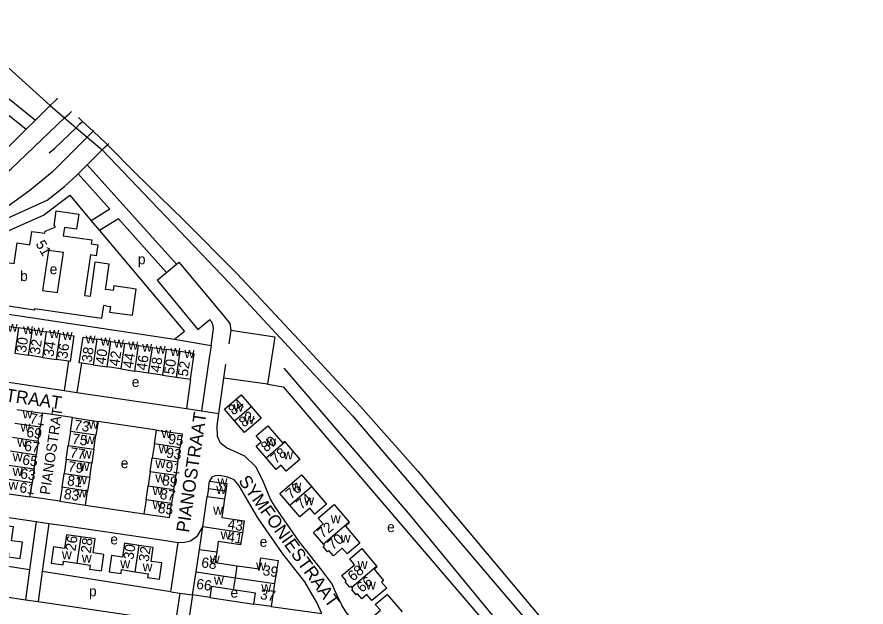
# Model space of a CAD drawing. Extents: x 163012 to 165277, y 382513 to 383987.
# Drawn here: x 164465.3 to 164795.7, y 383246.2 to 383475.9 of the extents above; entities that cross this region are included whole.
import ezdxf

# ---------------------------------------------------------------- set-up
doc = ezdxf.new("R2010")
doc.units = 0
for name, color, linetype in [('BLT_Basislijn', 7, 'Continuous'), ('BLT_Bebouwing', 7, 'Continuous'), ('BLT_Centroide', 7, 'Continuous'), ('BLT_Huisnummer', 7, 'Continuous'), ('BLT_Huisnummer_ tussenligend', 7, 'Continuous'), ('BLT_Onderverdeling_panden', 7, 'Continuous'), ('BLT_Spoorlijn', 7, 'Continuous'), ('BLT_Straatnaam', 7, 'Continuous'), ('BLT_Straatnaam_verkleind', 7, 'Continuous')]:
    doc.layers.add(name, color=color, linetype=linetype)

msp = doc.modelspace()

# ---------------------------------------------------------------- linework, layer by layer
at = {"layer": 'BLT_Basislijn'}
for p, q in [((164478.25, 383441.42), (164439.84, 383475.94)), ((164443.57, 383458.99), (164472.51, 383435.75)), ((164440.42, 383455.11), (164468.93, 383432.21)), ((164481.12, 383444.25), (164480.19, 383443.33)), ((164481.12, 383444.25), (164481.16, 383444.29)), ((164472.51, 383435.75), (164478.25, 383441.42)), ((164480.19, 383443.33), (164478.25, 383441.42)), ((164478.25, 383441.42), (164483.88, 383436.63)), ((164483.88, 383436.63), (164485.59, 383438.26)), ((164485.59, 383438.26), (164486.57, 383439.19)), ((164468.93, 383432.21), (164472.51, 383435.75)), ((164483.88, 383436.63), (164488.33, 383432.83)), ((164488.33, 383432.83), (164489.83, 383434.29)), ((164489.83, 383434.29), (164490.86, 383435.28)), ((164490.86, 383435.28), (164490.94, 383435.36)), ((164488.33, 383432.83), (164492.66, 383429.15)), ((164494.94, 383431.43), (164493.94, 383430.43)), ((164495.22, 383431.71), (164494.94, 383431.43)), ((164495.22, 383431.71), (164495.23, 383431.72)), ((164493.94, 383430.43), (164492.66, 383429.15)), ((164492.66, 383429.15), (164498.51, 383424.17)), ((164492.68, 383418.39), (164498.51, 383424.17)), ((164498.51, 383424.17), (164499.54, 383425.19)), ((164499.54, 383425.19), (164500.51, 383426.13)), ((164500.51, 383426.13), (164501.04, 383426.65)), ((164501.04, 383426.65), (164501.12, 383426.72)), ((164492.01, 383417.71), (164489.12, 383414.87)), ((164492.01, 383417.71), (164492.68, 383418.39)), ((164492.68, 383418.39), (164527.36, 383379.65)), ((164483.85, 383409.96), (164488.62, 383414.37)), ((164489.12, 383414.87), (164488.62, 383414.37)), ((164489.12, 383414.87), (164501.42, 383401.13)), ((164501.42, 383401.13), (164494.23, 383396.59)), ((164494.23, 383396.59), (164497.48, 383392.73)), ((164504.8, 383397.35), (164497.48, 383392.73)), ((164504.8, 383397.35), (164523.51, 383376.45)), ((164523.51, 383376.45), (164527.36, 383379.65)), ((164527.36, 383379.65), (164528.33, 383380.45)), ((164528.33, 383380.45), (164545.52, 383359.76)), ((164526.66, 383350.3), (164436.89, 383363.9)), ((164540.84, 383347.9), (164541.69, 383353.59)), ((164548.52, 383353.98), (164547.82, 383348.68)), ((164540.84, 383347.9), (164526.66, 383350.3)), ((164485.44, 383341.88), (164483.68, 383330.5)), ((164430.95, 383338.32), (164483.68, 383330.5)), ((164490.44, 383341.14), (164488.63, 383329.76)), ((164545.83, 383335.34), (164546.64, 383340.77)), ((164569.12, 383339.18), (164618.34, 383281.77)), ((164532.79, 383334.87), (164531.23, 383323.44)), ((164543.87, 383321.57), (164545.83, 383335.34)), ((164562.8, 383332.89), (164545.83, 383335.34)), ((164483.68, 383330.5), (164488.63, 383329.76)), ((164488.63, 383329.76), (164531.23, 383323.44)), ((164486.91, 383319.94), (164475.22, 383321.64)), ((164531.23, 383323.44), (164537.09, 383322.57)), ((164537.09, 383322.57), (164543.87, 383321.57)), ((164519.59, 383315.1), (164496.87, 383318.46)), ((164482.05, 383287.35), (164470.37, 383289.07)), ((164422.18, 383286.98), (164472.78, 383279.48)), ((164492.02, 383285.89), (164514.74, 383282.51)), ((164472.78, 383279.48), (164470.22, 383260.71)), ((164472.78, 383279.48), (164477.73, 383278.74)), ((164477.73, 383278.74), (164475.16, 383260)), ((164618.34, 383281.77), (164675.25, 383212.82)), ((164525.25, 383252.1), (164528.08, 383271.3)), ((164470.22, 383260.71), (164419.17, 383268.26)), ((164470.22, 383260.71), (164468.61, 383248.99)), ((164475.16, 383260), (164473.56, 383248.26)), ((164525.25, 383252.1), (164475.16, 383260)), ((164415.81, 383256.75), (164468.61, 383248.99)), ((164468.61, 383248.99), (164473.56, 383248.26)), ((164525.25, 383252.1), (164528.72, 383251.59)), ((164528.72, 383251.59), (164527.05, 383240.36)), ((164528.72, 383251.59), (164533.67, 383250.86)), ((164533.67, 383250.86), (164532, 383239.63)), ((164540.41, 383249.85), (164557.47, 383247.29)), ((164473.56, 383248.26), (164527.05, 383240.36)), ((164564.25, 383246.32), (164583.93, 383243.61))]:
    msp.add_line(p, q, dxfattribs=at)
for points in [[(164442.4, 383407.17), (164446.92, 383403.55), (164463.13, 383416.86), (164483.88, 383436.63)], [(164442.4, 383407.17), (164451.54, 383415.02), (164468.93, 383432.21)], [(164477.83, 383422.99), (164479.91, 383424.68), (164488.33, 383432.83)], [(164492.66, 383429.15), (164478.98, 383415.5), (164470.27, 383408.43), (164454.19, 383396.85), (164454, 383394.51)], [(164498.51, 383424.17), (164547.81, 383372.55), (164595.93, 383320.58), (164677.22, 383225), (164784.15, 383095.87), (164929, 382921.99), (164952.41, 382895.74), (164958.39, 382890.52), (164962.03, 382886.31)], [(164454, 383394.51), (164457.22, 383395.68), (164477.05, 383404.62), (164483.85, 383409.96)], [(164425.29, 383365.33), (164421.18, 383374.61), (164475.67, 383398.71), (164485.85, 383406.54), (164494.23, 383396.59)], [(164497.48, 383392.73), (164530.5, 383353.5), (164526.66, 383350.3)], [(164519.83, 383373.4), (164523.51, 383376.45)], [(164519.83, 383373.4), (164535.66, 383354.18), (164540.33, 383358.14)], [(164541.69, 383353.59), (164541.71, 383353.85), (164541.73, 383354.1), (164541.75, 383354.36), (164541.77, 383354.61), (164541.78, 383354.87), (164541.73, 383355.13), (164541.69, 383355.39), (164541.65, 383355.65), (164541.6, 383355.91), (164541.53, 383356.16), (164541.42, 383356.4), (164541.32, 383356.64), (164541.21, 383356.88), (164541.1, 383357.12), (164540.96, 383357.33), (164540.8, 383357.53), (164540.65, 383357.73), (164540.49, 383357.94), (164540.33, 383358.14)], [(164545.52, 383359.76), (164548.21, 383356.52), (164548.52, 383353.98)], [(164548.52, 383353.98), (164565.67, 383351.32), (164562.8, 383332.89)], [(164540.84, 383347.9), (164540.25, 383343.92), (164537.09, 383322.57)], [(164562.8, 383332.89), (164568.93, 383331.94), (164670.85, 383212.75), (164670.97, 383212.04)], [(164607.92, 383222.62), (164607.01, 383225.56), (164605.47, 383228.83), (164602.51, 383233.14), (164598.6, 383237.85), (164593.37, 383244.13), (164591.74, 383246.83), (164589.96, 383250.69), (164587.82, 383255.29), (164583.93, 383260.51), (164575.19, 383271.62), (164565.77, 383285.23), (164564.04, 383288.21), (164560.96, 383295.47), (164558.3, 383300.8), (164554.01, 383304.97), (164546.83, 383308.1), (164544.52, 383310.04), (164543.38, 383312.54), (164543.19, 383316.78), (164543.87, 383321.57)], [(164583.93, 383243.61), (164582.01, 383247.92), (164577.33, 383255.95), (164568.75, 383266.86), (164559.01, 383280.94), (164551.84, 383293.3), (164549.85, 383295.64), (164547.05, 383296.9), (164544.02, 383297.39), (164542.43, 383297.3), (164541.15, 383296.74), (164540.25, 383295.22)], [(164477.73, 383278.74), (164482.67, 383278.03), (164522.34, 383272.15), (164528.08, 383271.3)], [(164528.08, 383271.3), (164530.46, 383271.42), (164532.79, 383271.95), (164535.59, 383273.85), (164537.6, 383277.36)]]:
    msp.add_lwpolyline(points, dxfattribs=at)
at = {"layer": 'BLT_Bebouwing'}
for p, q in [((164499.78, 383369.86), (164500, 383371.4)), ((164500, 383369.83), (164499.78, 383369.86)), ((164498.97, 383363.55), (164498.26, 383358.53)), ((164500, 383363.4), (164498.97, 383363.55)), ((164460.52, 383355.73), (164465.92, 383354.93)), ((164471.32, 383354.13), (164465.92, 383354.93)), ((164471.32, 383354.13), (164476.72, 383353.33)), ((164482.12, 383352.53), (164476.72, 383353.33)), ((164501.83, 383349.61), (164496.43, 383350.41)), ((164501.83, 383349.61), (164507.23, 383348.81)), ((164512.63, 383348.01), (164507.23, 383348.81)), ((164512.63, 383348.01), (164518.03, 383347.21)), ((164464.45, 383344.99), (164469.85, 383344.19)), ((164518.03, 383347.21), (164523.44, 383346.41)), ((164528.84, 383345.61), (164523.44, 383346.41)), ((164475.25, 383343.39), (164469.85, 383344.19)), ((164475.25, 383343.39), (164480.65, 383342.59)), ((164485.44, 383341.88), (164480.65, 383342.59)), ((164494.96, 383340.47), (164490.44, 383341.14)), ((164494.96, 383340.47), (164500.36, 383339.67)), ((164505.76, 383338.87), (164500.36, 383339.67)), ((164505.76, 383338.87), (164511.16, 383338.07)), ((164516.56, 383337.27), (164511.16, 383338.07)), ((164521.96, 383336.47), (164516.56, 383337.27)), ((164521.96, 383336.47), (164527.36, 383335.67)), ((164465.26, 383323.12), (164475.22, 383321.64)), ((164475.22, 383321.64), (164474.41, 383316.22)), ((164486.1, 383314.51), (164486.91, 383319.94)), ((164486.91, 383319.94), (164496.87, 383318.46)), ((164496.87, 383318.46), (164496.06, 383313.04)), ((164473.6, 383310.79), (164474.41, 383316.22)), ((164518.78, 383309.66), (164519.59, 383315.1)), ((164519.59, 383315.1), (164529.55, 383313.61)), ((164486.1, 383314.51), (164485.29, 383309.08)), ((164495.25, 383307.6), (164496.06, 383313.04)), ((164529.55, 383313.61), (164528.75, 383308.19)), ((164473.6, 383310.79), (164472.79, 383305.36)), ((164484.48, 383303.65), (164485.29, 383309.08)), ((164518.78, 383309.66), (164517.97, 383304.23)), ((164471.99, 383299.93), (164472.79, 383305.36)), ((164495.25, 383307.6), (164494.45, 383302.17)), ((164527.94, 383302.76), (164528.75, 383308.19)), ((164484.48, 383303.65), (164483.67, 383298.21)), ((164493.64, 383296.74), (164494.45, 383302.17)), ((164517.17, 383298.8), (164517.97, 383304.23)), ((164527.94, 383302.76), (164527.13, 383297.33)), ((164471.99, 383299.93), (164471.18, 383294.49)), ((164517.17, 383298.8), (164516.36, 383293.37)), ((164482.86, 383292.78), (164483.67, 383298.21)), ((164493.64, 383296.74), (164492.83, 383291.31)), ((164526.32, 383291.9), (164527.13, 383297.33)), ((164539.8, 383292.22), (164540.25, 383295.22)), ((164470.37, 383289.07), (164471.18, 383294.49)), ((164482.86, 383292.78), (164482.05, 383287.35)), ((164515.55, 383287.94), (164516.36, 383293.37)), ((164526.32, 383291.9), (164525.51, 383286.47)), ((164539.8, 383292.22), (164539.36, 383289.25)), ((164460.4, 383290.54), (164470.37, 383289.07)), ((164492.02, 383285.89), (164492.83, 383291.31)), ((164537.6, 383277.36), (164539.36, 383289.25)), ((164546.54, 383291.22), (164546.11, 383288.25)), ((164482.05, 383287.35), (164492.02, 383285.89)), ((164515.55, 383287.94), (164514.74, 383282.51)), ((164524.71, 383281.05), (164525.51, 383286.47)), ((164514.74, 383282.51), (164524.71, 383281.05)), ((164536.3, 383268.6), (164537.6, 383277.36)), ((164543.65, 383271.66), (164543.05, 383267.6)), ((164535, 383259.85), (164536.3, 383268.6)), ((164533.67, 383250.86), (164535, 383259.85)), ((164565.58, 383255.32), (164564.25, 383246.32)), ((164540.41, 383249.85), (164533.67, 383250.86)), ((164564.25, 383246.32), (164557.47, 383247.29))]:
    msp.add_line(p, q, dxfattribs=at)
for points in [[(164445.85, 383365.73), (164448.2, 383382.26), (164464.26, 383379.98), (164465.4, 383387.97), (164470.33, 383387.27), (164471.06, 383392.44), (164476.19, 383391.71), (164476.3, 383392.47), (164480.14, 383394.04), (164480.24, 383394.52), (164479.74, 383394.63), (164480.6, 383400.43), (164489.39, 383399.13), (164488.53, 383393.29), (164483.85, 383393.94), (164483.29, 383390.7), (164494.41, 383389.12), (164494.19, 383387.59), (164496.79, 383387.22), (164496.19, 383382.97), (164493.96, 383383.29)], [(164493.97, 383383.3), (164491.62, 383367.51), (164493.9, 383367.19), (164495.77, 383380.43)], [(164500, 383371.4), (164501.18, 383379.66), (164495.77, 383380.43)], [(164500, 383363.4), (164501.68, 383363.14), (164501.38, 383361.03), (164510.23, 383359.78), (164511.68, 383370), (164502.99, 383371.24), (164502.74, 383369.48), (164500, 383369.83)], [(164498.26, 383358.53), (164472.16, 383362.24), (164472.1, 383361.83), (164445.85, 383365.73)], [(164482.12, 383352.53), (164487.48, 383351.74)], [(164487.48, 383351.74), (164486.01, 383341.8), (164485.44, 383341.88)], [(164490.44, 383341.14), (164489.56, 383341.27), (164491.03, 383351.21)], [(164491.03, 383351.21), (164496.43, 383350.41)], [(164534.26, 383344.81), (164528.84, 383345.61)], [(164532.79, 383334.87), (164534.26, 383344.81)], [(164527.36, 383335.67), (164532.79, 383334.87)], [(164549.97, 383318.71), (164546.07, 383323.26), (164552.58, 383328.82), (164556.47, 383324.28)], [(164556.47, 383324.28), (164560.36, 383319.74), (164553.86, 383314.18), (164549.97, 383318.71)], [(164562.33, 383304.28), (164558.44, 383308.81), (164558.44, 383308.81), (164560.38, 383310.48), (164558.41, 383312.77), (164562.97, 383316.67), (164562.97, 383316.67), (164568.68, 383310.06), (164569.45, 383310.71), (164569.6, 383310.52)], [(164569.6, 383310.52), (164569.6, 383310.52), (164575.45, 383303.65), (164570.11, 383299.11), (164568.16, 383301.4), (164566.22, 383299.75), (164562.33, 383304.28), (164562.33, 383304.28)], [(164540.25, 383295.22), (164546.98, 383294.22), (164546.54, 383291.22)], [(164571.53, 383285.85), (164567.63, 383290.39), (164567.63, 383290.39), (164576.05, 383297.61), (164579.95, 383293.07)], [(164579.95, 383293.07), (164585.8, 383286.25), (164585.8, 383286.25), (164581.24, 383282.34), (164579.3, 383284.61), (164579.3, 383284.61), (164575.43, 383281.31), (164571.53, 383285.85)], [(164546.11, 383288.25), (164545.06, 383281.02), (164553.76, 383279.73), (164553.07, 383275.07)], [(164584.55, 383270.66), (164580.66, 383275.21), (164584.5, 383278.5), (164582.55, 383280.79), (164582.55, 383280.79), (164582.55, 383280.79), (164588.79, 383286.09), (164588.79, 383286.09), (164594.61, 383279.27)], [(164594.61, 383279.27), (164594.77, 383279.08), (164593.11, 383277.66), (164593.11, 383277.66), (164598.79, 383271.03), (164593.88, 383266.82), (164591.93, 383269.11), (164588.44, 383266.12), (164586.72, 383268.12), (164586.21, 383267.68), (164584.45, 383269.76), (164584.94, 383270.2), (164584.55, 383270.66)], [(164456.9, 383267.98), (164462.1, 383267.17), (164461.88, 383265.69), (164466.52, 383265.02), (164467.44, 383271.39), (164463.23, 383271.99), (164463.99, 383277.36), (164458.43, 383278.19)], [(164490.17, 383273.48), (164484.59, 383274.31), (164483.79, 383268.95), (164479.56, 383269.59), (164478.62, 383263.23), (164483.26, 383262.54), (164483.48, 383264.02), (164488.65, 383263.22)], [(164488.65, 383263.22), (164493.81, 383262.42), (164493.6, 383260.94), (164498.27, 383260.31), (164499.19, 383266.68), (164494.98, 383267.29), (164495.74, 383272.66), (164490.17, 383273.48)], [(164553.07, 383275.07), (164552.37, 383270.37), (164543.65, 383271.66)], [(164512.72, 383270.14), (164507.15, 383270.97), (164506.35, 383265.62), (164502.11, 383266.25), (164501.17, 383259.92), (164505.81, 383259.24), (164506.03, 383260.72), (164511.2, 383259.92)], [(164511.2, 383259.92), (164516.36, 383259.11), (164516.14, 383257.63), (164520.83, 383256.97), (164521.74, 383263.34), (164517.53, 383263.95), (164518.29, 383269.31), (164512.72, 383270.14)], [(164595.67, 383253.87), (164595.3, 383254.31), (164594.8, 383253.88), (164592.99, 383255.97), (164593.49, 383256.4), (164593.49, 383256.4), (164591.75, 383258.41), (164591.75, 383258.41), (164596.73, 383262.66), (164594.79, 383264.94), (164599.46, 383268.92), (164605.25, 383262.09), (164605.25, 383262.09)], [(164543.05, 383267.6), (164542.44, 383263.51), (164551, 383262.24)], [(164551, 383262.24), (164559.53, 383260.98), (164560.18, 383265.29), (164566.91, 383264.3), (164565.58, 383255.32)], [(164605.25, 383262.09), (164605.25, 383262.09), (164605.46, 383261.85), (164604.3, 383260.87), (164604.3, 383260.87), (164608.01, 383256.5), (164607.24, 383255.85), (164609.2, 383253.55), (164609.2, 383253.55), (164603.45, 383248.68), (164601.51, 383250.98), (164599.56, 383249.31), (164597.86, 383251.29), (164597.36, 383250.86), (164595.57, 383252.95), (164596.07, 383253.39), (164595.67, 383253.87), (164595.67, 383253.87)], [(164549.61, 383252.88), (164541.05, 383254.15), (164540.41, 383249.85)], [(164557.47, 383247.29), (164558.15, 383251.62), (164549.61, 383252.88)], [(164606.79, 383237.05), (164602.89, 383241.6), (164606.73, 383244.88), (164604.76, 383247.16), (164604.76, 383247.16), (164609.33, 383251.08), (164615.2, 383244.26)]]:
    msp.add_lwpolyline(points, dxfattribs=at)
msp.add_lwpolyline([(164477.63, 383385.06), (164475.31, 383369.49), (164481.14, 383368.62), (164483.45, 383384.19)], close=True, dxfattribs=at)
at = {"layer": 'BLT_Onderverdeling_panden'}
for p, q in [((164465.92, 383354.93), (164464.45, 383344.99)), ((164469.85, 383344.19), (164471.32, 383354.13)), ((164476.72, 383353.33), (164475.25, 383343.39)), ((164480.65, 383342.59), (164482.12, 383352.53)), ((164496.43, 383350.41), (164494.96, 383340.47)), ((164500.36, 383339.67), (164501.83, 383349.61)), ((164507.23, 383348.81), (164505.76, 383338.87)), ((164511.16, 383338.07), (164512.63, 383348.01)), ((164516.56, 383337.27), (164518.03, 383347.21)), ((164523.44, 383346.41), (164521.96, 383336.47)), ((164527.36, 383335.67), (164528.84, 383345.61)), ((164549.97, 383318.71), (164556.47, 383324.28)), ((164474.41, 383316.22), (164464.45, 383317.69)), ((164463.64, 383312.26), (164473.6, 383310.79)), ((164496.06, 383313.04), (164486.1, 383314.51)), ((164485.29, 383309.08), (164495.25, 383307.6)), ((164528.75, 383308.19), (164518.78, 383309.66)), ((164472.79, 383305.36), (164462.83, 383306.83)), ((164494.45, 383302.17), (164484.48, 383303.65)), ((164517.97, 383304.23), (164527.94, 383302.76)), ((164462.02, 383301.4), (164471.99, 383299.93)), ((164527.13, 383297.33), (164517.17, 383298.8)), ((164471.18, 383294.49), (164461.21, 383295.97)), ((164483.67, 383298.21), (164493.64, 383296.74)), ((164492.83, 383291.31), (164482.86, 383292.78)), ((164516.36, 383293.37), (164526.32, 383291.9)), ((164546.54, 383291.22), (164539.8, 383292.22)), ((164539.36, 383289.25), (164546.11, 383288.25)), ((164525.51, 383286.47), (164515.55, 383287.94)), ((164594.61, 383279.27), (164584.55, 383270.66)), ((164553.07, 383275.07), (164537.6, 383277.36)), ((164490.17, 383273.48), (164488.65, 383263.22)), ((164512.72, 383270.14), (164511.2, 383259.92)), ((164536.3, 383268.6), (164543.05, 383267.6)), ((164550.31, 383257.58), (164551, 383262.24)), ((164535, 383259.85), (164550.31, 383257.58)), ((164595.67, 383253.87), (164605.25, 383262.09)), ((164549.61, 383252.88), (164550.31, 383257.58)), ((164550.31, 383257.58), (164565.58, 383255.32))]:
    msp.add_line(p, q, dxfattribs=at)
for points in [[(164562.33, 383304.28), (164562.33, 383304.28), (164569.6, 383310.52), (164569.6, 383310.52)], [(164571.53, 383285.85), (164571.53, 383285.85), (164579.95, 383293.07), (164579.95, 383293.07)]]:
    msp.add_lwpolyline(points, dxfattribs=at)
at = {"layer": 'BLT_Spoorlijn'}
for points in [[(164489.32, 383436.74), (164490.86, 383435.28)], [(164490.86, 383435.28), (164494.94, 383431.43)], [(164494.94, 383431.43), (164500, 383426.64)], [(164500.51, 383426.13), (164500, 383426.64)], [(164580.53, 383344.18), (164551.04, 383375.93), (164530.09, 383396.89), (164511.43, 383415.15), (164500.51, 383426.13)], [(164580.53, 383344.18), (164598.99, 383324.26), (164621.39, 383298.94), (164677.23, 383232.33)]]:
    msp.add_lwpolyline(points, dxfattribs=at)

# ---------------------------------------------------------------- texts
at = {"layer": 'BLT_Centroide'}
for s, p in [('p', (164512.37, 383379.63)), ('e', (164478.06, 383375.75)), ('b', (164466.55, 383373.1)), ('w', (164461.68, 383353.33)), ('w', (164467.71, 383352.44)), ('w', (164471.85, 383351.82)), ('w', (164477.92, 383350.92)), ('w', (164483.09, 383350.16)), ('w', (164492.05, 383348.83)), ('w', (164497.86, 383347.97)), ('w', (164503.09, 383347.2)), ('w', (164508.62, 383346.38)), ('w', (164514.05, 383345.57)), ('w', (164519.32, 383344.79)), ('w', (164525.04, 383343.95)), ('w', (164530.52, 383343.14)), ('e', (164510.01, 383331.84)), ('w', (164549.57, 383322.21)), ('w', (164467.53, 383319.6)), ('w', (164493.12, 383315.59)), ('w', (164553.79, 383317.42)), ('w', (164466.7, 383314.45)), ('w', (164521.52, 383312.01)), ('w', (164491.76, 383309.6)), ('w', (164562.24, 383308.63)), ('w', (164465.41, 383308.54)), ('w', (164520.46, 383306.03)), ('w', (164463.67, 383302.94)), ('w', (164490.55, 383304)), ('w', (164568.91, 383303.62)), ('w', (164489.64, 383299.15)), ('e', (164505.7, 383300.24)), ('w', (164519.18, 383300.27)), ('w', (164463.67, 383297.18)), ('w', (164488.73, 383293.93)), ('w', (164519.18, 383294.74)), ('w', (164543.35, 383293.22)), ('w', (164462, 383291.81)), ('w', (164488.73, 383288.85)), ('w', (164518.12, 383289.74)), ('w', (164542.89, 383290.16)), ('w', (164572.14, 383291.49)), ('w', (164577.08, 383285.82)), ('w', (164518.12, 383284.29)), ('w', (164541.66, 383282.12)), ('w', (164587.43, 383278.76)), ('w', (164544.58, 383272.53)), ('e', (164609.36, 383275.34)), ('e', (164501.66, 383270.56)), ('e', (164559.77, 383269.61)), ('w', (164591.31, 383271.19)), ('w', (164482.8, 383264.78)), ('w', (164490.55, 383263.41)), ('w', (164540.38, 383263.12)), ('w', (164505.52, 383261.22)), ('w', (164514.21, 383260.04)), ('w', (164558.41, 383260.31)), ('w', (164597.88, 383260.97)), ('w', (164541.97, 383254.88)), ('w', (164601.1, 383252.92)), ('p', (164493.36, 383250.33)), ('e', (164548.42, 383249.81)), ('w', (164560.41, 383251.97))]:
    msp.add_text(s, height=4, dxfattribs=at).set_placement(p)
at = {"layer": 'BLT_Huisnummer'}
for s, rotation, p in [('51', 300.4122, (164472.43, 383387.57)), ('30', 81.5821, (164468.83, 383345.04)), ('34', 81.5821, (164479.52, 383343.46)), ('38', 81.5821, (164494.38, 383341.27)), ('42', 81.5821, (164505.07, 383339.71)), ('46', 81.5821, (164515.75, 383338.1)), ('50', 81.5821, (164526.43, 383336.53)), ('52', 81.5821, (164531.78, 383335.76)), ('84', 39.8502, (164549.57, 383320.64)), ('71', 351.5821, (164470.09, 383317.76)), ('82', 39.8502, (164553.7, 383315.96)), ('73', 351.5821, (164487.37, 383315.2)), ('95', 351.5821, (164523.97, 383309.79)), ('80', 39.8502, (164562.28, 383306.26)), ('77', 351.5821, (164485.71, 383304.46)), ('65', 351.5821, (164467.21, 383301.71)), ('78', 39.8502, (164566.07, 383301.73)), ('89', 351.5821, (164521.57, 383293.66)), ('61', 351.5821, (164466.1, 383290.89)), ('83', 351.5821, (164483.38, 383288.33)), ('76', 39.8502, (164571.92, 383288.01)), ('74', 39.8502, (164576, 383283.9)), ('85', 351.5821, (164519.98, 383282.91)), ('43', 351.5816, (164547.1, 383276.62)), ('72', 39.8502, (164584.24, 383272.75)), ('41', 351.6879, (164546.93, 383271.66)), ('26', 81.5821, (164488.06, 383267.77)), ('28', 81.5821, (164493.99, 383266.9)), ('70', 39.8502, (164588.21, 383268.21)), ('30', 81.5821, (164510.61, 383264.44)), ('32', 81.5821, (164516.55, 383263.58)), ('68', 352.0077, (164536.87, 383261.65)), ('39', 351.5816, (164560.75, 383258.61)), ('68', 39.8502, (164596.1, 383256.01)), ('66', 351.5816, (164534.91, 383253.31)), ('66', 39.8502, (164599.55, 383251.62)), ('37', 351.5816, (164559.76, 383249.29))]:
    msp.add_text(s, height=4, rotation=rotation, dxfattribs=at).set_placement(p)
at = {"layer": 'BLT_Huisnummer_ tussenligend'}
for s, rotation, p in [('32', 81.5821, (164474.18, 383344.27)), ('36', 81.5821, (164484.86, 383342.67)), ('40', 81.5821, (164499.72, 383340.48)), ('44', 81.5821, (164510.41, 383338.9)), ('48', 81.5821, (164521.09, 383337.32)), ('69', 351.5821, (164468.81, 383312.46)), ('75', 351.5821, (164486.57, 383309.83)), ('67', 351.5821, (164467.96, 383307.09)), ('93', 351.5821, (164523.17, 383304.41)), ('79', 351.5821, (164484.97, 383299.08)), ('91', 351.5821, (164522.85, 383298.97)), ('63', 351.5821, (164466.42, 383296.33)), ('81', 351.5821, (164484.65, 383293.63)), ('87', 351.5821, (164520.72, 383288.3))]:
    msp.add_text(s, height=4, rotation=rotation, dxfattribs=at).set_placement(p)
at = {"layer": 'BLT_Straatnaam'}
for s, rotation, p in [('HARPSTRAAT', 351.5769, (164437.84, 383329.72)), ('PIANOSTRAAT', 81.5769, (164532.21, 383274.97)), ('SYMFONIESTRAAT', 305.7191, (164551.29, 383295.21))]:
    msp.add_text(s, height=5, rotation=rotation, dxfattribs=at).set_placement(p)
at = {"layer": 'BLT_Straatnaam_verkleind'}
msp.add_text('PIANOSTRAT', height=4, rotation=81.5928, dxfattribs=at).set_placement((164478.1, 383289.69))

doc.saveas('drawing.dxf')
